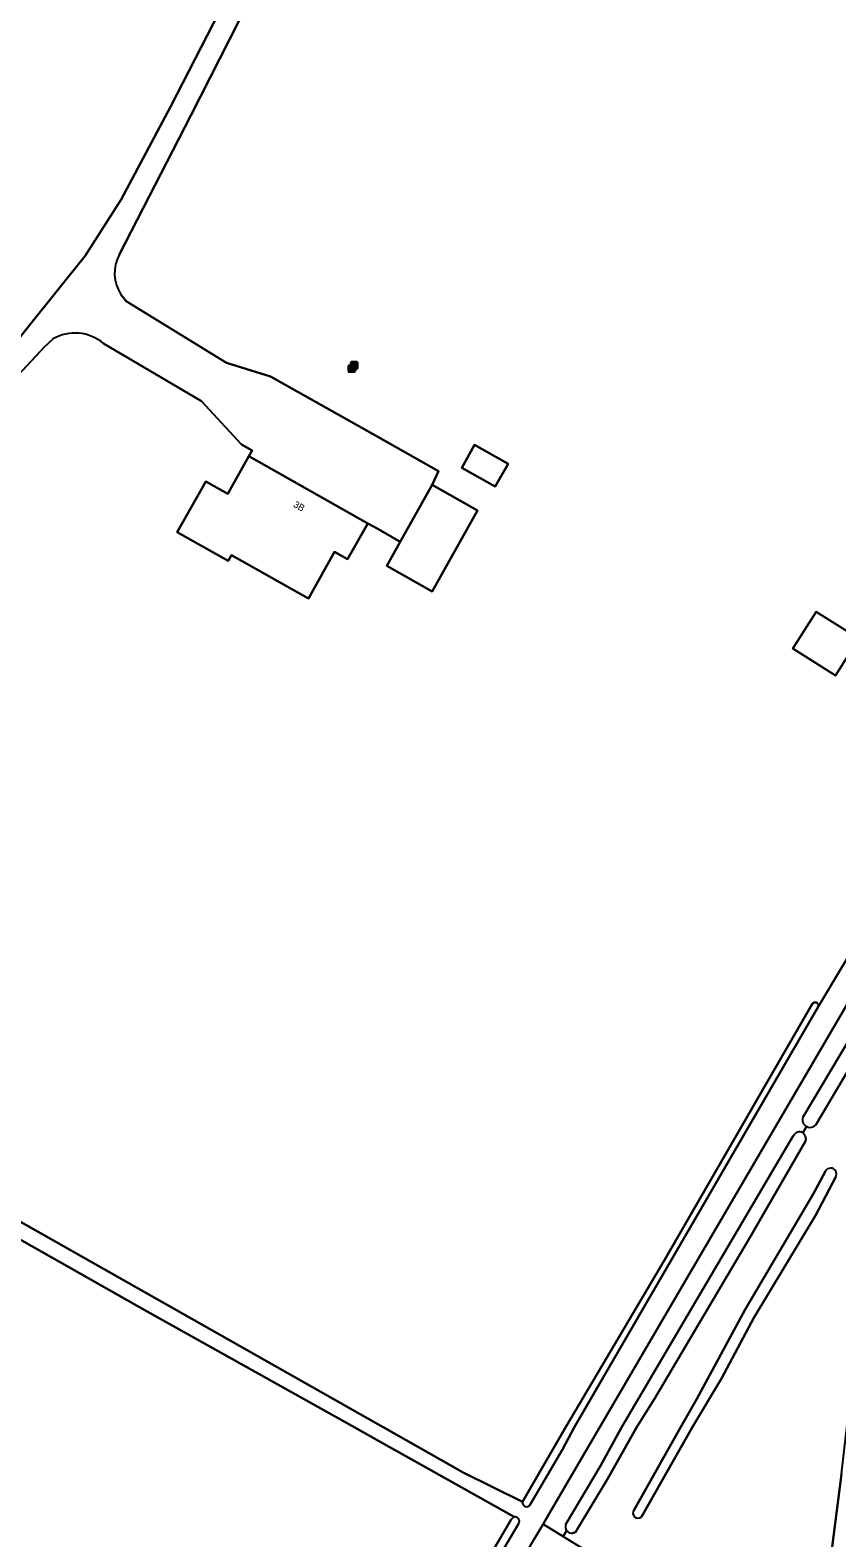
# Model space of a CAD drawing. Extents: x 156502 to 159075, y 384229 to 386100.
# Drawn here: x 157448.6 to 157567.8, y 385483.7 to 385706.5 of the extents above; entities that cross this region are included whole.
import ezdxf

# ---------------------------------------------------------------- set-up
doc = ezdxf.new("R2010")
doc.units = 0
for name, color, linetype in [('IMGEO_Gemengd_bos', 7, 'Continuous'), ('IMGEO_Grasland_overig', 7, 'Continuous'), ('IMGEO_Kast', 7, 'Continuous'), ('IMGEO_Pand', 7, 'Continuous'), ('IMGEO_Pand_nummerreeks', 7, 'Continuous'), ('IMGEO_Rijbaan_lokaal_onverhard', 7, 'Continuous'), ('IMGEO_Rioolput', 7, 'Continuous'), ('IMGEO_Voetpad_onverhard', 7, 'Continuous'), ('IMGEO_Waterloop', 7, 'Continuous')]:
    doc.layers.add(name, color=color, linetype=linetype)

msp = doc.modelspace()

# ---------------------------------------------------------------- linework, layer by layer
at = {"layer": 'IMGEO_Gemengd_bos'}
for points in [[(157488.94, 385433.84), (157500, 385452.75), (157519.69, 385486.42), (157520.17, 385486.79), (157500, 385498.1), (157496.61, 385500), (157465.92, 385517.13), (157304.76, 385608.45)], [(157593.43, 385593.63), (157579.04, 385568.85), (157564.72, 385544.74)], [(157563.38, 385544.48), (157562.8, 385543.56)], [(157563.23, 385542.35), (157554.95, 385527.97), (157540.88, 385504.22), (157538.22, 385500), (157533.99, 385492.46), (157529.21, 385484.53), (157528.79, 385484.37)], [(157537.87, 385487.83), (157544.75, 385500), (157547.12, 385504.14), (157554.28, 385517.46), (157564.36, 385534.5), (157566.16, 385537.9)], [(157567.68, 385537.04), (157564.7, 385531.34), (157555.56, 385516.2), (157550.79, 385507.26)], [(157527.9, 385484.75), (157527.38, 385483.91), (157530.62, 385481.92), (157563.46, 385465.6), (157564.31, 385466.5), (157566.43, 385476.59), (157568.55, 385493.1), (157569.3, 385500), (157570.14, 385505.9), (157572.71, 385515.89)], [(157550.79, 385507.26), (157546.45, 385500.01), (157538.96, 385486.81)]]:
    msp.add_lwpolyline(points, dxfattribs=at)
for centre, radius, start, end in [((157562.3, 385542.7), 0.99, 339.2697, 59.8635), ((157563.88, 385545.48), 1.12, 243.5538, 318.7532), ((157566.92, 385537.47), 0.872, 329.9347, 150.7876), ((157538.45, 385487.35), 0.747, 140.0413, 313.3281), ((157528.67, 385485.31), 0.949, 216.3662, 277.1269)]:
    msp.add_arc(centre, radius, start, end, dxfattribs=at)
at = {"layer": 'IMGEO_Grasland_overig'}
for points in [[(157469.41, 385695.31), (157486.39, 385728.38)], [(157489.43, 385727.47), (157472.35, 385693.94), (157461.79, 385673.34)], [(157654.39, 385706.53), (157603.44, 385620.84), (157569.84, 385563.4), (157525.21, 385487.09), (157524.42, 385485.73), (157527.38, 385483.91), (157527.9, 385484.75)], [(157565.07, 385562.16), (157597.46, 385616.26), (157622.7, 385659.17), (157649.3, 385705.76)], [(157428.49, 385636.04), (157434.2, 385644.32), (157444.33, 385657.68), (157448.58, 385663), (157456.75, 385673.2), (157462.07, 385681.52), (157469.41, 385695.31)], [(157462.04, 385667.45), (157462.83, 385666.5), (157477.64, 385657.38), (157484.15, 385655.36), (157500, 385646.42), (157508.98, 385641.36), (157508.04, 385639.31), (157514.74, 385635.54), (157508.03, 385623.59), (157501.32, 385627.36), (157503.32, 385630.92), (157500, 385632.81), (157498.53, 385633.64), (157495.52, 385628.33), (157493.61, 385629.42), (157489.76, 385622.53), (157478.38, 385628.96), (157477.89, 385628.08), (157470.37, 385632.33), (157474.6, 385639.8), (157477.82, 385638), (157478.13, 385638.55), (157480.95, 385643.56), (157481.43, 385644.4), (157479.85, 385645.29), (157473.93, 385651.68), (157459.47, 385660.23)], [(157451.96, 385660.88), (157450.69, 385659.68), (157446.91, 385655.6), (157436.78, 385642.24), (157431.08, 385633.96)], [(157562.85, 385545.92), (157573.9, 385564.45), (157591.43, 385594.65)], [(157349.49, 385585.71), (157500, 385500.51), (157500.9, 385500), (157512.64, 385493.35), (157521.37, 385489.04), (157527.74, 385500), (157542.42, 385524.85), (157564.22, 385562.66), (157564.48, 385562.84), (157564.8, 385562.83)], [(157562.8, 385543.56), (157563.38, 385544.48)], [(157527.81, 385485.7), (157532.9, 385494.33), (157536.03, 385500), (157561.41, 385543.13)]]:
    msp.add_lwpolyline(points, dxfattribs=at)
for points in [[(157514.3, 385645.23), (157519.27, 385642.44), (157517.37, 385639.06), (157512.4, 385641.85)], [(157564.77, 385620.58), (157571.07, 385616.62), (157567.63, 385611.15), (157561.33, 385615.12)]]:
    msp.add_lwpolyline(points, close=True, dxfattribs=at)
for centre, radius, start, end in [((157466.91, 385670.61), 5.8, 151.9587, 212.9274), ((157455.24, 385655.16), 6.6, 50.155, 119.8127), ((157564.61, 385562.36), 0.499, 336.1591, 68.653), ((157563.88, 385545.48), 1.12, 156.7312, 243.4456), ((157562.31, 385542.7), 0.989, 59.8353, 154.4919), ((157528.67, 385485.31), 0.947, 155.396, 216.3221)]:
    msp.add_arc(centre, radius, start, end, dxfattribs=at)
at = {"layer": 'IMGEO_Kast'}
for p, q in [((157496, 385656.57), (157496, 385657.41)), ((157496, 385657.41), (157496, 385656.57)), ((157496.07, 385657.49), (157496.92, 385657.49)), ((157496.92, 385657.49), (157496.07, 385657.49)), ((157497, 385657.42), (157497, 385656.58)), ((157497, 385656.58), (157497, 385657.42)), ((157496.93, 385656.49), (157496.08, 385656.49)), ((157496.08, 385656.49), (157496.93, 385656.49))]:
    msp.add_line(p, q, dxfattribs=at)
for points in [[(157496.2, 385657.28), (157496.8, 385657.28), (157496.8, 385657.2), (157496.2, 385657.2), (157496.2, 385657.28)], [(157496.2, 385657.11), (157496.8, 385657.11), (157496.8, 385656.62), (157496.2, 385656.62), (157496.2, 385657.11)]]:
    msp.add_lwpolyline(points, dxfattribs=at)
msp.add_circle((157496.28, 385656.96), 0.0377, dxfattribs=at)
for centre, start, end in [((157496.08, 385657.41), 92.4484, 184.2845), ((157496.08, 385657.41), 92.4484, 184.2845), ((157496.92, 385657.41), 2.4484, 94.2845), ((157496.92, 385657.41), 2.4484, 94.2845), ((157496.08, 385656.57), 182.4484, 274.2845), ((157496.08, 385656.57), 182.4484, 274.2845), ((157496.92, 385656.57), 272.4484, 4.2845), ((157496.92, 385656.57), 272.4484, 4.2845)]:
    msp.add_arc(centre, 0.0779, start, end, dxfattribs=at)
at = {"layer": 'IMGEO_Pand'}
for points in [[(157512.4, 385641.85), (157517.37, 385639.06), (157519.27, 385642.44), (157514.3, 385645.23)], [(157480.95, 385643.56), (157478.13, 385638.55), (157477.82, 385638), (157474.6, 385639.8), (157470.37, 385632.33), (157477.89, 385628.08), (157478.38, 385628.96), (157489.76, 385622.53), (157493.61, 385629.42), (157495.52, 385628.33), (157498.53, 385633.64)], [(157501.32, 385627.36), (157508.03, 385623.59), (157514.74, 385635.54), (157508.04, 385639.31), (157503.32, 385630.92)], [(157561.33, 385615.12), (157567.63, 385611.15), (157571.07, 385616.62), (157564.77, 385620.58)]]:
    msp.add_lwpolyline(points, close=True, dxfattribs=at)
at = {"layer": 'IMGEO_Rijbaan_lokaal_onverhard'}
for points in [[(157525.18, 385784.84), (157533.58, 385780.37), (157586.31, 385750), (157622.39, 385728.89), (157639.61, 385718.2), (157643.25, 385715.53), (157646.92, 385712.09), (157648.8, 385709.08), (157649.3, 385707.38), (157649.3, 385705.76), (157622.7, 385659.17), (157597.46, 385616.26), (157565.07, 385562.16), (157529.02, 385500), (157527.3, 385496.76), (157522.49, 385488.54)], [(157486.39, 385728.38), (157469.41, 385695.31), (157462.07, 385681.52), (157456.75, 385673.2), (157448.58, 385663), (157444.33, 385657.68), (157434.2, 385644.32), (157428.49, 385636.04)], [(157461.79, 385673.34), (157472.35, 385693.94), (157489.43, 385727.47)], [(157396.69, 385267.41), (157430.07, 385324.6), (157448.24, 385355.38), (157450.16, 385358.87), (157451, 385360.33), (157484.41, 385418.25), (157514.88, 385469.42), (157523.11, 385483.49), (157524.42, 385485.73), (157525.21, 385487.09), (157569.84, 385563.4), (157603.44, 385620.84), (157654.39, 385706.53)], [(157459.47, 385660.23), (157473.93, 385651.68), (157479.85, 385645.29), (157481.43, 385644.4), (157480.95, 385643.56), (157498.53, 385633.64), (157500, 385632.81), (157503.32, 385630.92), (157508.04, 385639.31), (157508.98, 385641.36), (157500, 385646.42), (157484.15, 385655.36), (157477.64, 385657.38), (157462.83, 385666.5), (157462.04, 385667.45)], [(157446.91, 385655.6), (157450.69, 385659.68), (157451.96, 385660.88)], [(157489.01, 385433.16), (157339.5, 385517.4), (157316.57, 385530.13), (157289.4, 385546.39), (157298.5, 385584.05), (157304.76, 385608.45), (157465.92, 385517.13)], [(157521.37, 385489.04), (157512.64, 385493.35), (157500.9, 385500), (157500, 385500.51), (157349.49, 385585.71)], [(157465.92, 385517.13), (157496.61, 385500), (157500, 385498.1), (157520.17, 385486.79)], [(157520.78, 385485.76), (157500, 385450.48), (157489.84, 385433.23)]]:
    msp.add_lwpolyline(points, dxfattribs=at)
for centre, radius, start, end in [((157466.91, 385670.61), 5.8, 151.9587, 212.9274), ((157455.24, 385655.16), 6.6, 50.155, 119.8127), ((157522, 385488.93), 0.633, 170.2986, 254.343), ((157522, 385488.93), 0.63, 254.3056, 322.0481), ((157520.28, 385486.16), 0.638, 47.5282, 99.3683), ((157520.28, 385486.15), 0.642, 321.8479, 47.7229)]:
    msp.add_arc(centre, radius, start, end, dxfattribs=at)
at = {"layer": 'IMGEO_Rioolput'}
for p, q in [((157495.65, 385656.06), (157495.65, 385656.92)), ((157495.72, 385656.99), (157496.58, 385656.99)), ((157496.58, 385655.99), (157495.72, 385655.99)), ((157495.91, 385656.48), (157495.91, 385656.5)), ((157495.95, 385656.53), (157496.35, 385656.53)), ((157496.34, 385656.45), (157495.95, 385656.45)), ((157496.16, 385656.21), (157496.13, 385656.21)), ((157496.14, 385656.77), (157496.16, 385656.77)), ((157496.39, 385656.5), (157496.39, 385656.48)), ((157496.65, 385656.92), (157496.65, 385656.06))]:
    msp.add_line(p, q, dxfattribs=at)
for points in [[(157495.65, 385656.06), (157495.65, 385656.92)], [(157495.72, 385656.99), (157496.58, 385656.99)], [(157496.58, 385655.99), (157495.72, 385655.99)], [(157496.65, 385656.92), (157496.65, 385656.06)]]:
    msp.add_lwpolyline(points, dxfattribs=at)
for centre, radius, start, end in [((157495.72, 385656.91), 0.0765, 91.552, 178.448), ((157495.72, 385656.91), 0.0765, 91.552, 178.448), ((157495.72, 385656.07), 0.0765, 181.552, 268.448), ((157495.72, 385656.07), 0.0765, 181.552, 268.448), ((157495.95, 385656.49), 0.0403, 85.8775, 175.7526), ((157495.94, 385656.48), 0.0366, 178.938, 274.7102), ((157496.35, 385656.49), 0.043, 264.8664, 352.4533), ((157496.35, 385656.49), 0.0386, 1.7309, 96.639), ((157496.57, 385656.91), 0.0765, 1.552, 88.448), ((157496.57, 385656.91), 0.0765, 1.552, 88.448), ((157496.57, 385656.07), 0.0765, 271.552, 358.448), ((157496.57, 385656.07), 0.0765, 271.552, 358.448)]:
    msp.add_arc(centre, radius, start, end, dxfattribs=at)
for centre, major_axis, ratio, start_param, end_param in [((157496.14, 385656.49), (-0.387, 0.002), 0.722429, 4.712389, 7.853982), ((157496.16, 385656.49), (-0.39, 0.002), 0.717154, 1.570796, 4.712389)]:
    msp.add_ellipse(centre, major_axis=major_axis, ratio=ratio, start_param=start_param, end_param=end_param, dxfattribs=at)
at = {"layer": 'IMGEO_Voetpad_onverhard'}
for points in [[(157568.55, 385493.1), (157566.43, 385476.59)], [(157530.62, 385481.92), (157527.38, 385483.91), (157524.42, 385485.73), (157523.11, 385483.49)]]:
    msp.add_lwpolyline(points, dxfattribs=at)
at = {"layer": 'IMGEO_Waterloop'}
for points in [[(157591.43, 385594.65), (157573.9, 385564.45), (157562.85, 385545.92)], [(157564.72, 385544.74), (157579.04, 385568.85), (157593.43, 385593.63)], [(157564.8, 385562.83), (157564.48, 385562.84), (157564.22, 385562.66), (157542.42, 385524.85), (157527.74, 385500), (157521.37, 385489.04)], [(157522.49, 385488.54), (157527.3, 385496.76), (157529.02, 385500), (157565.07, 385562.16)], [(157561.41, 385543.13), (157536.03, 385500), (157532.9, 385494.33), (157527.81, 385485.7)], [(157554.95, 385527.97), (157563.23, 385542.35)], [(157566.16, 385537.9), (157564.36, 385534.5), (157554.28, 385517.46), (157547.12, 385504.14), (157544.75, 385500), (157537.87, 385487.83)], [(157538.96, 385486.81), (157546.45, 385500.01), (157550.79, 385507.26), (157555.56, 385516.2), (157564.7, 385531.34), (157567.68, 385537.04)], [(157528.79, 385484.37), (157529.21, 385484.53), (157533.99, 385492.46), (157538.22, 385500), (157540.88, 385504.22), (157554.95, 385527.97)], [(157520.17, 385486.79), (157519.69, 385486.42), (157500, 385452.75), (157488.94, 385433.84)], [(157489.84, 385433.23), (157500, 385450.48), (157520.78, 385485.76)]]:
    msp.add_lwpolyline(points, dxfattribs=at)
for centre, radius, start, end in [((157564.61, 385562.36), 0.499, 336.1591, 68.653), ((157563.88, 385545.48), 1.12, 156.7312, 243.4456), ((157562.31, 385542.7), 0.989, 59.8353, 154.4919), ((157562.3, 385542.7), 0.99, 339.2697, 59.8635), ((157563.88, 385545.48), 1.12, 243.5538, 318.7532), ((157566.92, 385537.47), 0.872, 329.9347, 150.7876), ((157522, 385488.93), 0.633, 170.2986, 254.343), ((157522, 385488.93), 0.63, 254.3056, 322.0481), ((157538.45, 385487.35), 0.747, 140.0413, 313.3281), ((157520.28, 385486.16), 0.638, 47.5282, 99.3683), ((157520.28, 385486.15), 0.642, 321.8479, 47.7229), ((157528.67, 385485.31), 0.947, 155.396, 216.3221), ((157528.67, 385485.31), 0.949, 216.3662, 277.1269)]:
    msp.add_arc(centre, radius, start, end, dxfattribs=at)

# ---------------------------------------------------------------- texts
at = {"layer": 'IMGEO_Pand_nummerreeks'}
msp.add_text('3B', height=1, rotation=330.5841, dxfattribs=at).set_placement((157487.43, 385636.14))

doc.saveas('drawing.dxf')
